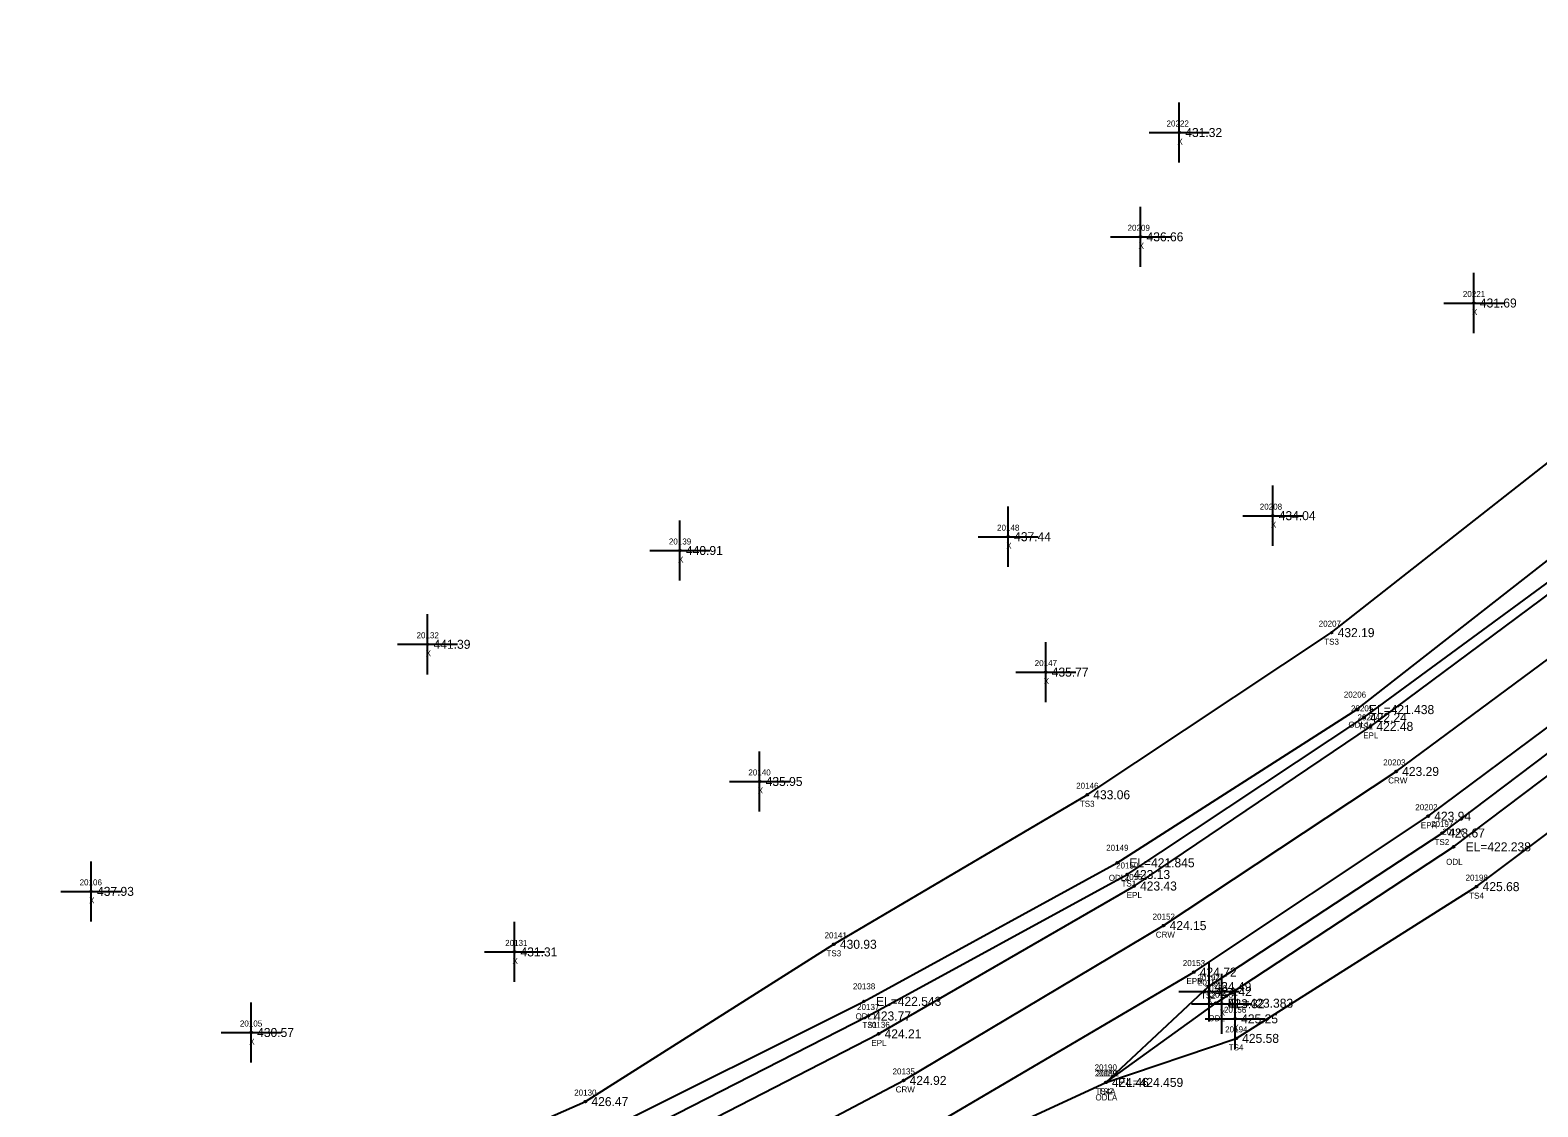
# Model space of a CAD drawing. Extents: x 2116373 to 2118139, y 979529 to 981026.
# Drawn here: x 2116755.3 to 2117006.3, y 979768.8 to 979948 of the extents above; entities that cross this region are included whole.
import ezdxf

# ---------------------------------------------------------------- set-up
doc = ezdxf.new("R2010")
doc.units = 0
for name, color, linetype in [('RD_DTM_BkLn1', 7, 'Continuous'), ('RD_DTM_BkLn2', 7, 'Continuous'), ('RD_DTM_BkLn_txCode', 7, 'Continuous'), ('RD_EX_H2O', 7, 'Continuous'), ('RD_EX_H2O_txCode', 7, 'Continuous'), ('RD_EX_Misc', 7, 'Continuous'), ('RD_EX_Misc_txCode', 7, 'Continuous'), ('RD_EX_Road', 7, 'Continuous'), ('RD_EX_Road_txCode', 7, 'Continuous'), ('RD_EX_TX_H2O_ELEV', 7, 'Continuous'), ('RD_EX_TX_Misc_ELEV', 7, 'Continuous'), ('RD_EX_TX_Road_ELEV', 7, 'Continuous'), ('RD_HC_Survey_ELEV', 7, 'Continuous'), ('RD_HC_Survey_txCode', 7, 'Continuous'), ('RD_SMD_Locator', 7, 'Continuous')]:
    doc.layers.add(name, color=color, linetype=linetype)

msp = doc.modelspace()

# ---------------------------------------------------------------- linework, layer by layer
at = {"layer": 'RD_DTM_BkLn1'}
msp.add_lwpolyline([(2116414.21, 979630.19), (2116468.62, 979643.23), (2116521.45, 979653.6), (2116618.87, 979670.38), (2116668.4, 979680.7), (2116717.3, 979694.48), (2116764.56, 979711.13), (2116810.15, 979729.38), (2116856.49, 979749.81), (2116900.74, 979773.15), (2116944.03, 979798.93), (2116982.75, 979824.6), (2117026.56, 979857.02), (2117064.34, 979888.81), (2117101.78, 979922.69), (2117176.3, 979989.4), (2117250.99, 980056.19), (2117326.56, 980126.36)], dxfattribs=at)
at = {"layer": 'RD_DTM_BkLn2'}
for points in [[(2116410.78, 979641.79), (2116465.45, 979654.97), (2116518.83, 979664.89), (2116614.96, 979683.75), (2116663.75, 979692.58), (2116713.02, 979705.22), (2116760.07, 979721.97), (2116804.88, 979741.47), (2116850.79, 979761.38), (2116894.83, 979783.88), (2116937.98, 979807.44), (2116977.39, 979833.6), (2117020.56, 979865.29), (2117056.86, 979896.38), (2117094.29, 979932.2), (2117168.14, 979997.38), (2117238.71, 980069.61), (2117312.33, 980134.21), (2117318.43, 980135.16)], [(2116408.48, 979653.74), (2116461.38, 979665.42), (2116520.7, 979678.48), (2116616.28, 979695.74), (2116661.37, 979703.79), (2116711.18, 979715.21), (2116757.77, 979732.03), (2116802.04, 979749.54), (2116847.76, 979769.63), (2116889.13, 979795.82), (2116931.32, 979820.72), (2116972.01, 979847.71), (2117009.67, 979877.33), (2117051.05, 979910.18), (2117086.71, 979942.74), (2117161.4, 980003.96), (2117222.13, 980080.24), (2117265.44, 980120.03)], [(2116417.57, 979618.2), (2116471.29, 979630.11), (2116523.91, 979640.31), (2116563.87, 979646.21), (2116622.92, 979650.9), (2116673.37, 979660.68), (2116721.38, 979672.44), (2116775.31, 979687.3), (2116820.23, 979708.52), (2116865.35, 979734.51), (2116907.21, 979760.29), (2116934.42, 979772.82), (2116951.5, 979788.78), (2116990.39, 979814.35), (2117033.97, 979847.22), (2117071.26, 979879.46), (2117111.32, 979914.45), (2117184.14, 979980.37), (2117264.18, 980040.84), (2117335.34, 980108.05), (2117336.43, 980115.6)], [(2116934.42, 979772.82), (2116956.11, 979780.15), (2116996.15, 979805.42), (2117040.3, 979838.56), (2117080.53, 979868.79), (2117120.95, 979906.28), (2117189.36, 979974.74), (2117275.31, 980029.9), (2117344.8, 980095.54)]]:
    msp.add_lwpolyline(points, dxfattribs=at)
at = {"layer": 'RD_EX_H2O'}
for points in [[(2116411.09, 979644.42), (2116463.93, 979657.73), (2116517.88, 979668.38), (2116615.09, 979686.35), (2116663.35, 979695.16), (2116711.62, 979708.91), (2116758.49, 979726.13), (2116778.25, 979736.27), (2116803.5, 979744.47), (2116849.89, 979764.23), (2116894.14, 979786.32), (2116936.31, 979809.39), (2116976.21, 979834.9), (2117018.41, 979867.86), (2117054.24, 979898.91), (2117093.35, 979934.14), (2117166.11, 979999.69), (2117224.07, 980077.92), (2117265.44, 980120.03)], [(2116934.42, 979772.82), (2116952.72, 979786.01), (2116992.31, 979812.05), (2117036.21, 979845.2), (2117073.01, 979877), (2117113.79, 979913.05), (2117185.72, 979978.24), (2117270.2, 980032.33), (2117344.8, 980095.54)]]:
    msp.add_lwpolyline(points, dxfattribs=at)
at = {"layer": 'RD_EX_Misc'}
for p, q in [((2116946.64, 979925.99), (2116946.64, 979935.99)), ((2116941.64, 979930.99), (2116951.64, 979930.99)), ((2116940.19, 979908.62), (2116940.19, 979918.62)), ((2116935.19, 979913.62), (2116945.19, 979913.62)), ((2116995.69, 979897.6), (2116995.69, 979907.6)), ((2116990.69, 979902.6), (2117000.69, 979902.6)), ((2116962.2, 979862.19), (2116962.2, 979872.19)), ((2116918.14, 979858.69), (2116918.14, 979868.69)), ((2116863.5, 979856.39), (2116863.5, 979866.39)), ((2116957.2, 979867.19), (2116967.2, 979867.19)), ((2116913.14, 979863.69), (2116923.14, 979863.69)), ((2116858.5, 979861.39), (2116868.5, 979861.39)), ((2116821.48, 979840.77), (2116821.48, 979850.77)), ((2116816.48, 979845.77), (2116826.48, 979845.77)), ((2116924.4, 979836.14), (2116924.4, 979846.14)), ((2116919.4, 979841.14), (2116929.4, 979841.14)), ((2116876.77, 979817.93), (2116876.77, 979827.93)), ((2116871.77, 979822.93), (2116881.77, 979822.93)), ((2116765.44, 979799.63), (2116765.44, 979809.63)), ((2116760.44, 979804.63), (2116770.44, 979804.63)), ((2116835.95, 979789.55), (2116835.95, 979799.55)), ((2116830.95, 979794.55), (2116840.95, 979794.55)), ((2116951.59, 979782.96), (2116951.59, 979792.96)), ((2116953.7, 979780.92), (2116953.7, 979790.92)), ((2116946.59, 979787.96), (2116956.59, 979787.96)), ((2116955.94, 979778.41), (2116955.94, 979788.41)), ((2116792.1, 979776.13), (2116792.1, 979786.13)), ((2116948.7, 979785.92), (2116958.7, 979785.92)), ((2116950.94, 979783.41), (2116960.94, 979783.41)), ((2116787.1, 979781.13), (2116797.1, 979781.13))]:
    msp.add_line(p, q, dxfattribs=at)
at = {"layer": 'RD_EX_Road'}
for points in [[(2116412.2, 979638.84), (2116468.17, 979651.36), (2116519.2, 979662.5), (2116617.24, 979678.85), (2116665.51, 979689.1), (2116714.23, 979702.46), (2116761.42, 979719.35), (2116806.99, 979737.42), (2116852.23, 979758.11), (2116896.57, 979780.91), (2116939.1, 979805.52), (2116978.46, 979832.1), (2117021.29, 979863.87), (2117058.15, 979895.61), (2117096.06, 979930.47), (2117170.14, 979995.71), (2117244.91, 980062.82), (2117320.63, 980133.49), (2117326.56, 980126.36)], [(2116416.36, 979621.21), (2116470.51, 979634.11), (2116523.97, 979644.68), (2116620.55, 979661.21), (2116670.7, 979671.96), (2116720.65, 979685.84), (2116767.66, 979702.22), (2116814.07, 979721.02), (2116860.35, 979742.3), (2116904.9, 979765.18), (2116949.06, 979791.19), (2116988.09, 979817.15), (2117031.94, 979849.78), (2117069.79, 979881.53), (2117108.89, 979916.38), (2117182.06, 979982.67), (2117257.56, 980049.29), (2117334.73, 980117.38), (2117326.56, 980126.36)]]:
    msp.add_lwpolyline(points, dxfattribs=at)
at = {"layer": 'RD_SMD_Locator'}
for centre in [(2116946.64, 979930.99), (2116940.19, 979913.62), (2116995.69, 979902.6), (2116962.2, 979867.19), (2116918.14, 979863.69), (2116863.5, 979861.39), (2116972.01, 979847.71), (2116821.48, 979845.77), (2116924.4, 979841.14), (2116976.21, 979834.9), (2116977.39, 979833.6), (2116978.46, 979832.1), (2116876.77, 979822.93), (2116982.75, 979824.6), (2116931.32, 979820.72), (2116988.09, 979817.15), (2116990.39, 979814.35), (2116992.31, 979812.05), (2116936.31, 979809.39), (2116937.98, 979807.44), (2116939.1, 979805.52), (2116996.15, 979805.42), (2116765.44, 979804.63), (2116944.03, 979798.93), (2116889.13, 979795.82), (2116835.95, 979794.55), (2116949.06, 979791.19), (2116951.5, 979788.78), (2116951.59, 979787.96), (2116894.14, 979786.32), (2116952.72, 979786.01), (2116953.7, 979785.92), (2116894.83, 979783.88), (2116955.94, 979783.41), (2116792.1, 979781.13), (2116896.57, 979780.91), (2116956.11, 979780.15), (2116900.74, 979773.15), (2116934.42, 979772.82), (2116934.42, 979772.82), (2116934.42, 979772.82), (2116847.76, 979769.63)]:
    msp.add_circle(centre, 0.15, dxfattribs=at)

# ---------------------------------------------------------------- texts
at = {"layer": 'RD_DTM_BkLn_txCode'}
for s, p in [('20207', (2116969.85, 979848.71)), ('TS3', (2116970.77, 979845.71)), ('20205', (2116975.23, 979834.6)), ('TS1', (2116976.43, 979831.6)), ('20146', (2116929.47, 979821.72)), ('TS3', (2116930.08, 979818.72)), ('20197', (2116988.55, 979815.35)), ('TS2', (2116989.14, 979812.35)), ('20150', (2116936.11, 979808.44)), ('20198', (2116994.31, 979806.42)), ('TS1', (2116937.02, 979805.44)), ('TS4', (2116994.9, 979803.42)), ('20141', (2116887.58, 979796.82)), ('TS3', (2116887.89, 979793.82)), ('20192', (2116949.66, 979789.78)), ('TS2', (2116950.26, 979786.78)), ('20137', (2116892.99, 979784.88)), ('TS1', (2116893.87, 979781.88)), ('20194', (2116954.28, 979781.15)), ('TS4', (2116954.87, 979778.15)), ('20189', (2116932.58, 979773.82)), ('20191', (2116932.87, 979773.82)), ('20130', (2116845.89, 979770.63)), ('TS4A', (2116932.68, 979770.82)), ('TS2', (2116933.17, 979770.82))]:
    msp.add_text(s, height=1, dxfattribs=at).set_placement(p)
at = {"layer": 'RD_EX_H2O_txCode'}
for s, p in [('20206', (2116974.03, 979836.9)), ('ODL1', (2116974.8, 979831.9)), ('20196', (2116990.45, 979814.05)), ('20149', (2116934.47, 979811.39)), ('ODL', (2116991.07, 979809.05)), ('ODL1', (2116934.9, 979806.39)), ('20138', (2116892.3, 979788.32)), ('20193', (2116950.88, 979788.01)), ('ODL1', (2116892.73, 979783.32)), ('ODL', (2116951.47, 979783.01)), ('20190', (2116932.54, 979774.82)), ('ODLA', (2116932.68, 979769.82))]:
    msp.add_text(s, height=1, dxfattribs=at).set_placement(p)
at = {"layer": 'RD_EX_Misc_txCode'}
for s, p in [('20222', (2116944.52, 979931.99)), ('X', (2116946.32, 979928.99)), ('20209', (2116938.03, 979914.62)), ('X', (2116939.87, 979911.62)), ('20221', (2116993.86, 979903.6)), ('X', (2116995.38, 979900.6)), ('20208', (2116960.04, 979868.19)), ('20148', (2116916.3, 979864.69)), ('X', (2116961.89, 979865.19)), ('20139', (2116861.66, 979862.39)), ('X', (2116917.82, 979861.69)), ('X', (2116863.18, 979859.39)), ('20132', (2116819.64, 979846.77)), ('X', (2116821.16, 979843.77)), ('20147', (2116922.56, 979842.14)), ('X', (2116924.08, 979839.14)), ('20140', (2116874.89, 979823.93)), ('X', (2116876.45, 979820.93)), ('20106', (2116763.54, 979805.63)), ('X', (2116765.12, 979802.63)), ('20131', (2116834.4, 979795.55)), ('X', (2116835.63, 979792.55)), ('20154', (2116949.75, 979788.96)), ('20155', (2116951.86, 979786.92)), ('X', (2116951.27, 979785.96)), ('X', (2116953.38, 979783.92)), ('20156', (2116954.08, 979784.41)), ('20105', (2116790.23, 979782.13)), ('X', (2116955.62, 979781.41)), ('X', (2116791.79, 979779.13))]:
    msp.add_text(s, height=1, dxfattribs=at).set_placement(p)
at = {"layer": 'RD_EX_Road_txCode'}
for s, p in [('20204', (2116976.31, 979833.1)), ('EPL', (2116977.26, 979830.1)), ('20202', (2116985.93, 979818.15)), ('EPR', (2116986.86, 979815.15)), ('20151', (2116937.55, 979806.52)), ('EPL', (2116937.89, 979803.52)), ('20153', (2116947.22, 979792.19)), ('EPR', (2116947.83, 979789.19)), ('20136', (2116894.72, 979781.91)), ('EPL', (2116895.37, 979778.91))]:
    msp.add_text(s, height=1, dxfattribs=at).set_placement(p)
at = {"layer": 'RD_EX_TX_H2O_ELEV'}
for s, p in [('EL=421.438', (2116978.21, 979834.15)), ('EL=422.238', (2116994.31, 979811.3)), ('EL=421.845', (2116938.31, 979808.64)), ('EL=422.543', (2116896.14, 979785.57)), ('EL=423.383', (2116954.72, 979785.26)), ('EL=424.459', (2116936.42, 979772.07))]:
    msp.add_text(s, height=1.5, dxfattribs=at).set_placement(p)
at = {"layer": 'RD_EX_TX_Misc_ELEV'}
for s, p in [('431.32', (2116947.64, 979930.24)), ('436.66', (2116941.19, 979912.87)), ('431.69', (2116996.69, 979901.85)), ('434.04', (2116963.2, 979866.44)), ('437.44', (2116919.14, 979862.94)), ('440.91', (2116864.5, 979860.64)), ('432.19', (2116973.01, 979846.96)), ('441.39', (2116822.48, 979845.02)), ('435.77', (2116925.4, 979840.39)), ('422.24', (2116978.39, 979832.85)), ('435.95', (2116877.77, 979822.18)), ('433.06', (2116932.32, 979819.97)), ('423.67', (2116991.39, 979813.6)), ('423.13', (2116938.98, 979806.69)), ('437.93', (2116766.44, 979803.88)), ('425.68', (2116997.15, 979804.67)), ('431.31', (2116836.95, 979793.8)), ('430.93', (2116890.13, 979795.07)), ('424.49', (2116952.5, 979788.03)), ('424.42', (2116952.59, 979787.21)), ('423.32', (2116954.7, 979785.17)), ('423.77', (2116895.83, 979783.13)), ('425.25', (2116956.94, 979782.66)), ('430.57', (2116793.1, 979780.38)), ('425.58', (2116957.11, 979779.4)), ('424.46', (2116935.42, 979772.07)), ('424.46', (2116935.42, 979772.07)), ('426.47', (2116848.76, 979768.88))]:
    msp.add_text(s, height=1.5, dxfattribs=at).set_placement(p)
at = {"layer": 'RD_EX_TX_Road_ELEV'}
for s, p in [('422.48', (2116979.46, 979831.35)), ('423.94', (2116989.09, 979816.4)), ('423.43', (2116940.1, 979804.77)), ('424.72', (2116950.06, 979790.44)), ('424.21', (2116897.57, 979780.16))]:
    msp.add_text(s, height=1.5, dxfattribs=at).set_placement(p)
at = {"layer": 'RD_HC_Survey_ELEV'}
for s, p in [('423.29', (2116983.75, 979823.85)), ('424.15', (2116945.03, 979798.18)), ('424.92', (2116901.74, 979772.4))]:
    msp.add_text(s, height=1.5, dxfattribs=at).set_placement(p)
at = {"layer": 'RD_HC_Survey_txCode'}
for s, p in [('20203', (2116980.59, 979825.6)), ('CRW', (2116981.43, 979822.6)), ('20152', (2116942.2, 979799.93)), ('CRW', (2116942.72, 979796.93)), ('20135', (2116898.9, 979774.15)), ('CRW', (2116899.42, 979771.15))]:
    msp.add_text(s, height=1, dxfattribs=at).set_placement(p)

doc.saveas('drawing.dxf')
